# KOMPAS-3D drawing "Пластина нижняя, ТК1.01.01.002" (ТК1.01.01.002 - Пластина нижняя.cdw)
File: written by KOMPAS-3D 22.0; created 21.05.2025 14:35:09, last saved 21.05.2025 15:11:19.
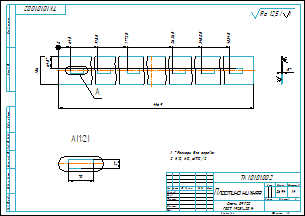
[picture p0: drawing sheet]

Sheet 1: A3, landscape

Document properties: Автор: user; Знак неуказанной шероховатости: 4; Параметр неуказанной шероховатости: Ra 12,5; Масса: 26.939167; Полное имя файла: ..\Пластина нижняя.m3d

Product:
- Part/product: Пластина нижняя  | designation ТК1.01.01.002
    Масса: 26.939167
    Форматы листов документа: A3

Title block, sheet 1: Наименование: Пластина нижняя; designation: ТК1.01.01.002; Материал: Сталь 09Г2С / ГОСТ 19281-2014; Масса: 26,94; scale: 1:4; Количество листов документа: 1; Форматы листов документа: A3; stored path: D:\Рабочая папка\АРХИВ\612\05\Задание №6 - Тележка для крыши\3Д\Тележка в сборе\Корпус тележки\КД\ТК1.01.01.002 - Пластина нижняя.cdw

Views: Проекционный вид 2, Выносной элемент 3, Проекционный вид 4, Выносной элемент А, Выносной элемент
Referenced files in D:\Рабочая папка\АРХИВ\612\05\Задание №6 - Тележка для крыши\3Д\Тележка в сборе\: Пластина нижняя.m3d
Referenced files in D:\Работа\2025\5. Май\Задание №6 - Тележка для крыши\3Д\Тележка в сборе\Корпус тележки\: Пластина нижняя.m3d
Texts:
  Ra 12,5
  Ra 12,5 ( )
  BOSimple***Material:4ccf0190-16b6-4223-9222-aa108d28a442
  ТК1.01.01.002 Пластина нижняя
Dimensions and other numbers on the sheet: 4469; 156; 64,5; 918,5; 1772,5; 2626,5; 3480,5; 4334,5; 7; 70; 27; 5; 1:4; 1; 26,94

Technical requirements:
  *Размеры для справок.
  H12, h12, ±IT12/2.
